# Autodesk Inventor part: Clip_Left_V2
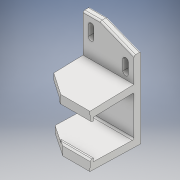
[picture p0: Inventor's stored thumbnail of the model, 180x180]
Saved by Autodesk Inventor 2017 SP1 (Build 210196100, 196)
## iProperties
Created: 2017-10
Part Number: Clip_Left_V2
Material: ABS Plastic
Document SubType Name: Modeling
Designer: Nick
Density: 1.06 g/cm^3
Appearance: Smooth - White
Created: 2017-12
Part Number: Clip_Left_V2_3DPrint
Material: Generic
Density: 1 g/cm^3
Appearance: Default
Author: Nick
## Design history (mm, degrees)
sketch "Sketch1"
  geometry: L1 (0, 0)-(0, -17.322); L2 (-4.4, 0)-(-4.4, -12.8); L3 (-32.11, -16.444)-(0, -17.322); L4 (-4.4, 0)-(0, 0); L5 (-32.11, -16.444)-(-31.935, -10.046); L6 (-31.935, -10.046)-(-29.936, -10.101); L7 (-29.99, -12.1)-(-29.936, -10.101); L8 (-4.4, -12.8)-(-29.99, -12.1); 3 further points; 1 other entity
  constraints: 16 end point, 3 perpendicular, 2 coincident, 1 horizontal, 1 parallel, 1 vertical, 2 other
  dimensions: "d0" = 4.4 distance between parallel lines of L1 L2; "d6" = 12.8 distance of L2.start L2.end; "d7" = 2 distance of L7.start L6.end; "d8" = 25.6 distance of L7.start L2.end (= 2 x d6); "d9" = 2 distance of L5.end L6.end; "d13" = 4.4 distance between parallel lines of L3 L8; "d14" = 0.7 vertical distance of L7.start L2.end; "d20" = 88.4331 deg angle of L3 L1 (derived)
extrude "Clamp half" new body sketch "Sketch1" distance "d10" = 32; taper "d11" = 0 deg
mirror "Clamp Mirror"
workplane "Work Plane1"
sketch "Sketch2"
  geometry: L1 (30.6, 22)-(1.4, 22); L2 (1.4, 22)-(1.4, 0); L3 (1.4, 0)-(30.6, 0); L4 (30.6, 0)-(30.6, 22); L5 (0, 0)-(32, 0) reference; L6 (28.6, 20.5)-(25.1, 20.5); L7 (25.1, 20.5)-(25.1, 18.75); L8 (25.1, 10.5)-(28.6, 10.5); L9 (28.6, 10.5)-(28.6, 12.25); L10 (28.6, 18.75)-(28.6, 20.5); L11 (25.1, 18.75)-(25.1, 12.25); L12 (25.1, 12.25)-(25.1, 10.5); L13 (28.6, 12.25)-(28.6, 18.75); L14 (16, 22)-(16, 0); L15 (3.4, 1)-(3.4, 2.75); L16 (3.4, 2.75)-(3.4, 9.25); L17 (3.4, 9.25)-(3.4, 11); L18 (6.9, 2.75)-(6.9, 1); L19 (6.9, 11)-(6.9, 9.25); L20 (6.9, 9.25)-(6.9, 2.75); A1 r 1.75 centre (26.85, 18.75) between (28.6, 18.75) and (25.1, 18.75); A2 r 1.75 centre (26.85, 12.25) between (25.1, 12.25) and (28.6, 12.25); A3 r 1.75 centre (5.15, 2.75) between (3.4, 2.75) and (6.9, 2.75); A4 r 1.75 centre (5.15, 9.25) between (6.9, 9.25) and (3.4, 9.25); 6 further points; 2 other entities
  constraints: 38 end point, 22 point on circle, 13 parallel, 6 vertical, 4 centre point, 4 horizontal alignment, 4 midpoint, 4 perpendicular, 4 point on line, 2 horizontal, 1 tangent, 1 vertical alignment, 8 other
  dimensions: "d16" = 29.2 distance of L1.start L1.end; "d17" = 22 distance of L3.end L1.start; "d21" = 3.5 distance of L6.start L6.end; "d22" = 10 distance of L6.end L8.start; "d23" = 1.75 radius of A1 (= 0.5 x d21); "d24" = 2 distance between parallel lines of L4 L9; "d25" = 1.5 distance from line of L1 L6.start; "d26" = 1.75 radius of A2 (= d23); "d27" = 18.2 distance between parallel lines of L11 L20; "d30" = 1.75 radius of A4 (= d23); "d31" = 1.75 radius of A3 (= d23); "d34" = 3.5 distance of L16.end L19.end (= d21); "d36" = 11 distance from line of L1 L17.end
extrude "Extrusion4" join sketch "Sketch2" distance "d28" = 3.2; taper "d29" = 0 deg
chamfer "Chamfer1" distance "d40" = 1; stored, may be unused: second distance "d41" = 2, angle "d42" = 45 deg
fillet "Fillet4" dims "d43" = 1
sketch "Sketch4"
  geometry: L1 (0, -34.644)-(0, -58.644); L2 (0, -58.644)-(11, -58.644); L3 (32, -50.244)-(32, -34.644); L4 (28.5, -36.644)-(25, -36.644); L5 (25, -36.644)-(25, -38.394); L6 (25, -46.644)-(28.5, -46.644); L7 (28.5, -46.644)-(28.5, -44.894); L8 (28.5, -38.394)-(28.5, -36.644); L9 (25, -38.394)-(25, -44.894); L10 (25, -44.894)-(25, -46.644); L11 (28.5, -44.894)-(28.5, -38.394); L12 (16, -34.644)-(16, -0.636); L13 (3.3, -54.644)-(3.3, -52.894); L14 (3.3, -52.894)-(3.3, -46.394); L15 (3.3, -46.394)-(3.3, -44.644); L16 (6.8, -52.894)-(6.8, -54.644); L17 (6.8, -54.644)-(3.3, -54.644); L18 (6.8, -44.644)-(6.8, -46.394); L19 (6.8, -46.394)-(6.8, -52.894); L20 (11, -58.644)-(32, -50.244); L21 (32, 0)-(32, -34.644) reference; L22 (0, -34.644)-(0, 0) reference; L23 (0, -34.644)-(32, -34.644) reference; L24 (32, -32.644)-(0, -32.644); A1 r 1.75 centre (26.75, -38.394) between (28.5, -38.394) and (25, -38.394); A2 r 1.75 centre (26.75, -44.894) between (25, -44.894) and (28.5, -44.894); A3 r 1.75 centre (5.05, -52.894) between (3.3, -52.894) and (6.8, -52.894); A4 r 1.75 centre (5.05, -46.394) between (6.8, -46.394) and (3.3, -46.394); 7 further points; 1 other entity
  constraints: 43 end point, 21 point on circle, 12 parallel, 6 point on line, 6 vertical, 4 centre point, 4 horizontal alignment, 4 perpendicular, 3 horizontal, 3 midpoint, 1 tangent, 1 vertical alignment, 4 other
  dimensions: "d45" = 24 distance of L3.end point (32, -58.644); "d46" = 3.5 distance of L4.start L4.end; "d47" = 10 distance of L4.end L6.start; "d48" = 1.75 radius of A1 (= 0.5 x d46); "d49" = 3.5 distance between parallel lines of L3 L7; "d51" = 1.75 radius of A2 (= d48); "d52" = 18.2 distance between parallel lines of L9 L19; "d53" = 1.75 radius of A4 (= d48); "d54" = 1.75 radius of A3 (= d48); "d55" = 3.5 distance of L14.end L18.end (= d46); "d59" = 4 distance from line of L2 point (5.05, -54.644) (derived); "d60" = 21 distance of L2.end point (32, -58.644); "d61" = 8.4 distance of L3.start point (32, -58.644) (= 0.4 x d60); "d65" = 2 distance from line of point (26.75, -36.644) L23; "d66" = 10 distance from line of L23 point (5.05, -44.644); "d69" = 2 distance between parallel lines of L24 L23
extrude "Extrusion7" join sketch "Sketch4" distance "d67" = 4.4; taper "d68" = 0 deg
fillet "Fillet5" dims "d70" = 1
sketch "Sketch6"
  geometry: L1 (20.113, -4.404)-(-8.336, 14.953); L2 (-8.336, 14.953)-(-8.336, -4.404); L3 (0, -0.899)-(32, -0.899) reference; L4 (-8.336, -4.404)-(20.113, -4.404); 1 further point
  constraints: 6 end point, 2 perpendicular
extrude "Extrusion8" cut sketch "Sketch6" stored distance "d71" = 4.4; taper "d72" = 0 deg
body "Solid2"
other parameters: "d15" = 7, "sa_0" = 0, "sa_1" = -781.25, "sa_2" = 19984.73539, "sa_3" = 0, "sa_4" = 0, "sa_5" = 50000
